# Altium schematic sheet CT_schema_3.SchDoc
size 186 x 156 mm
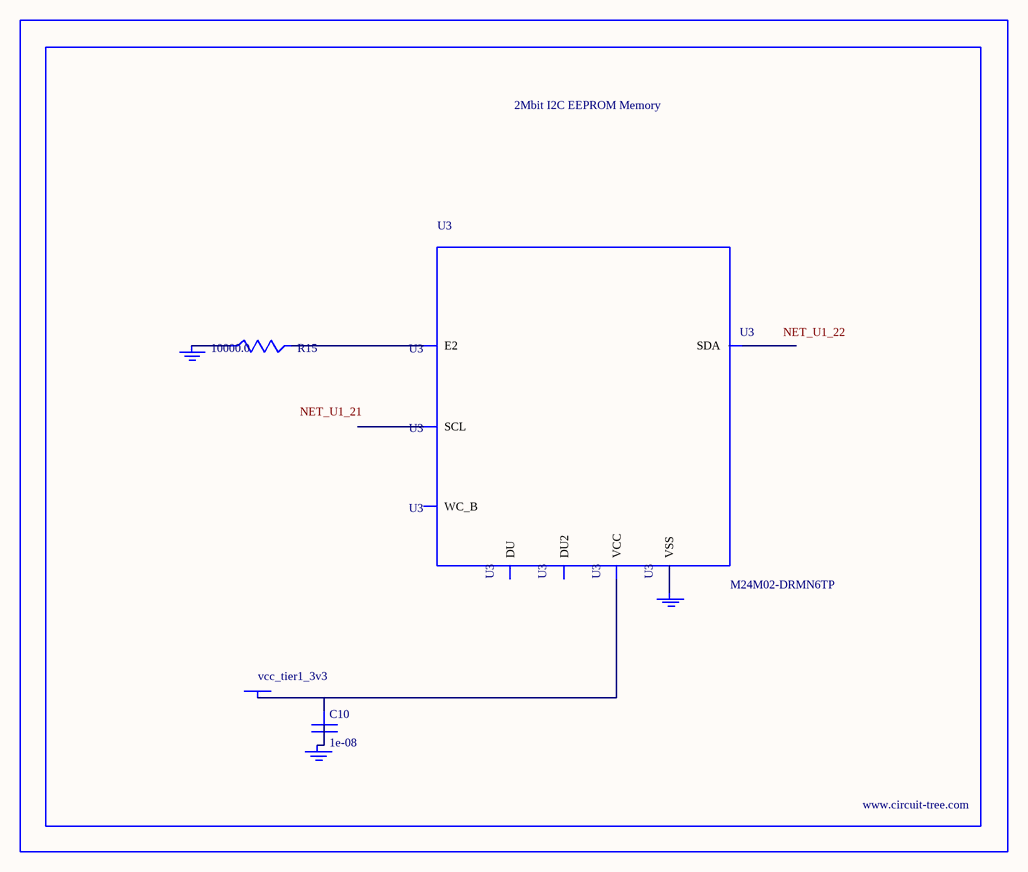
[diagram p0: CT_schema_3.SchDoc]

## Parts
BORDER2  (no value)
C10  1e-08  [C0402]
GND_INSTANCE_2_0  (no value)
GND_INSTANCE_2_1  (no value)
GND_INSTANCE_2_2  (no value)
POWER_INSTANCE_2_0  vcc_tier1_3v3
R15  10000.0  [R0603]
U3  M24M02-DRMN6TP  [SOIC-8]

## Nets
NetC10_1: C10.1 POWER_INSTANCE_2_0.0(PWR) U3.8(VCC)
NetC10_2: C10.2 GND_INSTANCE_2_1.0(GND)
NetGND_INSTANCE_2_0_0: GND_INSTANCE_2_0.0(GND) R15.1
NetGND_INSTANCE_2_2_0: GND_INSTANCE_2_2.0(GND) U3.4(VSS)
NetR15_2: R15.2 U3.3(E2)

Not connected (* = marked no-connect by the designer): U3 1(DU) 2(DU2) 5(SDA) 6(SCL) 7(WC_B)

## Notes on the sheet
- Labels drawn without touching a wire or pin: NET_U1_21, NET_U1_22

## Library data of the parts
BORDER2 = BORDER_PAGE2
C10 = C0402C103K3RAC
GND_INSTANCE_2_0-GND_INSTANCE_2_2 = GND
POWER_INSTANCE_2_0 = PWR
R15 = RC0603JR-0710KL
